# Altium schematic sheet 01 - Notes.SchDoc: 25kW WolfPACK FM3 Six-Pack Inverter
size 431 x 279 mm; Date: 01/2024; DocumentNumber: CRD25DA12N-FMC; Revision: 1.2; SheetNumber: 1; SheetTotal: 8; SheetSize: B
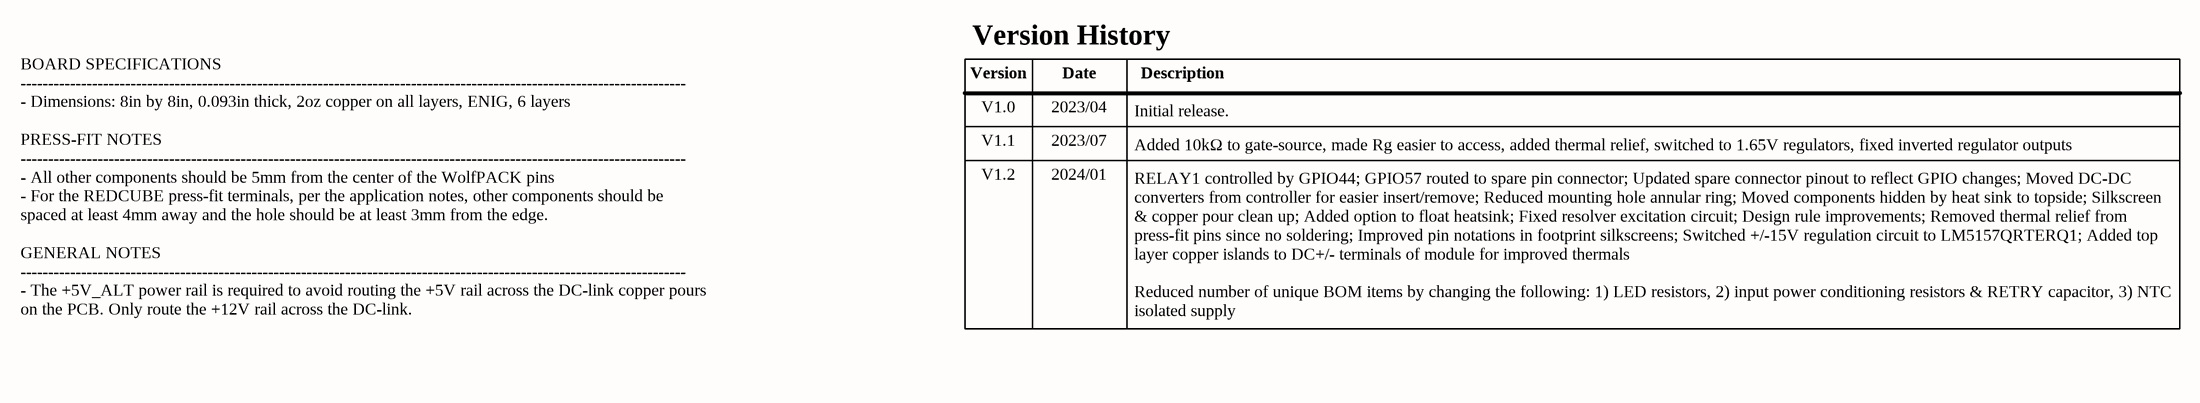
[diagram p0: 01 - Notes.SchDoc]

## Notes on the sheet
- Version History
- Version
- Date
- Description
- V1.0
- V1.1
- 2023/04
- 2023/07
- Initial release.
- Added 10kΩ to gate-source, made Rg easier to access, added thermal relief, switched to 1.65V regulators, fixed inverted regulator outputs
- V1.2
- 2024/01
- RELAY1 controlled by GPIO44; GPIO57 routed to spare pin connector; Updated spare connector pinout to reflect GPIO changes; Moved DC-DC converters from controller for easier insert/remove; Reduced mounting hole annular ring; Moved components hidden by heat sink to topside; Silkscreen & copper pour clean up; Added option to float heatsink; Fixed resolver excitation circuit; Design rule improvements; Removed thermal relief from press-fit pins since no soldering; Improved pin notations in footprint silkscreens; Switched +/-15V regulation circuit to LM5157QRTERQ1; Added top layer copper islands to DC+/- terminals of module for improved thermals
  Reduced number of unique BOM items by changing the following: 1) LED resistors, 2) input power conditioning resistors & RETRY capacitor, 3) NTC isolated supply
- BOARD SPECIFICATIONS
  -------------------------------------------------------------------------------------------------------------------------
  - Dimensions: 8in by 8in, 0.093in thick, 2oz copper on all layers, ENIG, 6 layers
  PRESS-FIT NOTES
  -------------------------------------------------------------------------------------------------------------------------
  - All other components should be 5mm from the center of the WolfPACK pins
  - For the REDCUBE press-fit terminals, per the application notes, other components should be spaced at least 4mm away and the hole should be at least 3mm from the edge.
  GENERAL NOTES
  -------------------------------------------------------------------------------------------------------------------------
  - The +5V_ALT power rail is required to avoid routing the +5V rail across the DC-link copper pours on the PCB. Only route the +12V rail across the DC-link.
